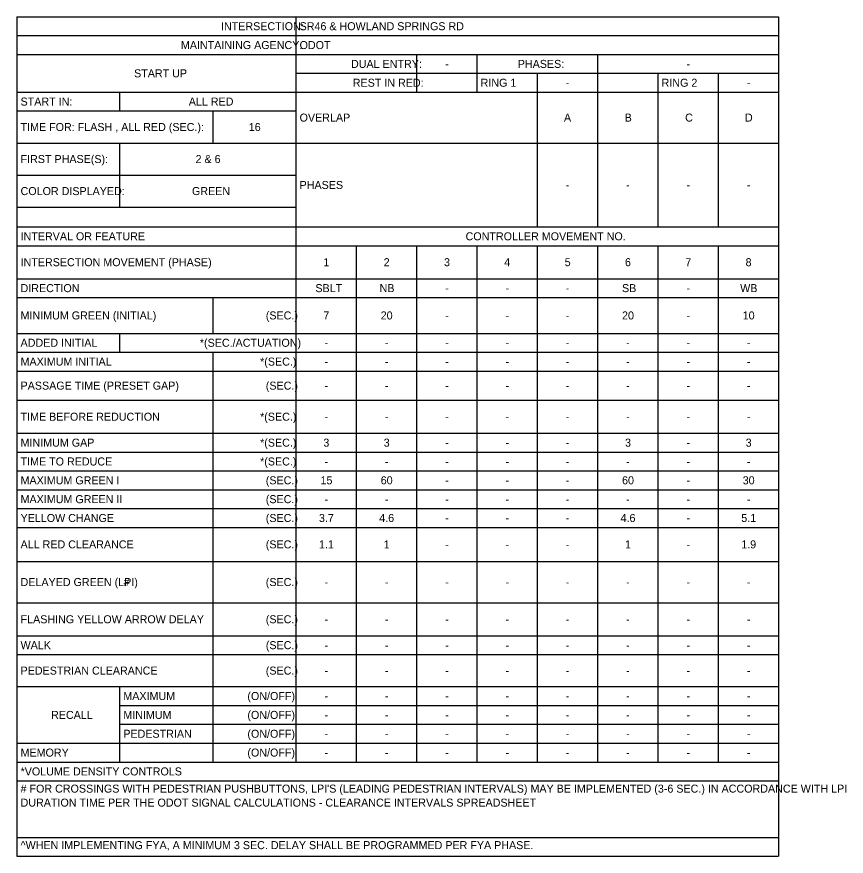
# Model space of a CAD drawing. Extents: x -513 to 1005, y -278 to 699.
# Drawn here: x -513 to -295.6, y -233.4 to -13.3 of the extents above; entities that cross this region are included whole.
import ezdxf

# ---------------------------------------------------------------- set-up
doc = ezdxf.new("R2010")
doc.units = 0
doc.layers.add('SG_P_Poles', color=7, linetype='Continuous')

msp = doc.modelspace()

# ---------------------------------------------------------------- linework, layer by layer
at = {"layer": 'SG_P_Poles'}
for p, q in [((-512.98, -13.26), (-313.35, -13.26)), ((-512.98, -13.26), (-512.98, -233.38)), ((-439.85, -13.26), (-439.85, -208.68)), ((-313.35, -13.26), (-313.35, -233.38)), ((-512.98, -18.2), (-313.35, -18.2)), ((-512.98, -23.14), (-313.35, -23.14)), ((-408.22, -23.14), (-408.22, -33.02)), ((-392.41, -23.14), (-392.41, -33.02)), ((-360.79, -23.14), (-360.79, -68.35)), ((-439.85, -28.08), (-313.35, -28.08)), ((-376.6, -28.08), (-376.6, -68.35)), ((-344.98, -28.08), (-344.98, -68.35)), ((-329.17, -28.08), (-329.17, -68.35)), ((-512.98, -33.02), (-313.35, -33.02)), ((-486.05, -33.02), (-486.05, -37.96)), ((-512.98, -37.96), (-439.85, -37.96)), ((-461.59, -37.96), (-461.59, -46.36)), ((-512.98, -46.36), (-313.35, -46.36)), ((-486.05, -46.36), (-486.05, -63.16)), ((-512.98, -54.76), (-439.85, -54.76)), ((-512.98, -63.16), (-439.85, -63.16)), ((-512.98, -68.35), (-313.35, -68.35)), ((-512.98, -73.29), (-313.35, -73.29)), ((-424.04, -73.29), (-424.04, -208.68)), ((-408.22, -73.29), (-408.22, -208.68)), ((-392.41, -73.29), (-392.41, -208.68)), ((-376.6, -73.29), (-376.6, -208.68)), ((-360.79, -73.29), (-360.79, -208.68)), ((-344.98, -73.29), (-344.98, -208.68)), ((-329.17, -73.29), (-329.17, -208.68)), ((-512.98, -81.94), (-313.35, -81.94)), ((-512.98, -86.88), (-313.35, -86.88)), ((-461.59, -86.88), (-461.59, -96.27)), ((-512.98, -96.27), (-313.35, -96.27)), ((-486.05, -96.27), (-486.05, -101.21)), ((-512.98, -101.21), (-313.35, -101.21)), ((-461.59, -101.21), (-461.59, -208.68)), ((-512.98, -106.15), (-313.35, -106.15)), ((-512.98, -113.81), (-313.35, -113.81)), ((-512.98, -122.46), (-313.35, -122.46)), ((-512.98, -127.4), (-313.35, -127.4)), ((-512.98, -132.34), (-313.35, -132.34)), ((-512.98, -137.28), (-313.35, -137.28)), ((-512.98, -142.22), (-313.35, -142.22)), ((-512.98, -147.16), (-313.35, -147.16)), ((-512.98, -156.06), (-313.35, -156.06)), ((-512.98, -166.93), (-313.35, -166.93)), ((-512.98, -175.57), (-313.35, -175.57)), ((-512.98, -180.51), (-313.35, -180.51)), ((-512.98, -188.91), (-313.35, -188.91)), ((-486.05, -188.91), (-486.05, -208.68)), ((-486.05, -193.86), (-313.35, -193.86)), ((-486.05, -198.8), (-313.35, -198.8)), ((-512.98, -203.74), (-313.35, -203.74)), ((-512.98, -208.68), (-313.35, -208.68)), ((-512.98, -213.62), (-313.35, -213.62)), ((-512.98, -228.44), (-313.35, -228.44)), ((-512.98, -233.38), (-313.35, -233.38))]:
    msp.add_line(p, q, dxfattribs=at)

# ---------------------------------------------------------------- texts
for s, p in [('INTERSECTION:', (-459.46, -16.78)), ('SR46 & HOWLAND SPRINGS RD', (-438.86, -16.78)), ('MAINTAINING AGENCY:', (-469.97, -21.72)), ('ODOT', (-438.86, -21.72)), ('DUAL ENTRY:', (-425.39, -26.66)), ('-', (-400.73, -26.66)), ('PHASES:', (-381.68, -26.66)), ('-', (-337.48, -26.66)), ('START UP', (-482.24, -29.13)), ('REST IN RED:', (-424.92, -31.6)), ('RING 1', (-391.42, -31.6)), ('-', (-369.11, -31.6)), ('RING 2', (-343.99, -31.6)), ('-', (-321.67, -31.6)), ('START IN:', (-511.99, -36.54)), ('ALL RED', (-467.9, -36.54)), ('OVERLAP', (-438.86, -40.74)), ('A', (-369.58, -40.74)), ('B', (-353.67, -40.74)), ('C', (-337.82, -40.74)), ('D', (-322.14, -40.74)), ('TIME FOR: FLASH , ALL RED (SEC.):', (-511.99, -43.21)), ('16', (-452.18, -43.21)), ('FIRST PHASE(S):', (-511.99, -51.61)), ('2 & 6', (-466.13, -51.61)), ('PHASES', (-438.86, -58.41)), ('COLOR DISPLAYED:', (-511.99, -60.01)), ('GREEN', (-467.07, -60.01)), ('-', (-369.11, -58.41)), ('-', (-353.3, -58.41)), ('-', (-337.48, -58.41)), ('-', (-321.67, -58.41)), ('INTERVAL OR FEATURE', (-511.99, -71.87)), ('CONTROLLER MOVEMENT NO.', (-395.36, -71.87)), ('INTERSECTION MOVEMENT (PHASE)', (-511.99, -78.66)), ('1', (-432.63, -78.66)), ('2', (-416.82, -78.66)), ('3', (-401.01, -78.66)), ('4', (-385.23, -78.66)), ('5', (-369.38, -78.66)), ('6', (-353.59, -78.66)), ('7', (-337.76, -78.66)), ('8', (-321.97, -78.66)), ('DIRECTION', (-511.99, -85.46)), ('SBLT', (-434.73, -85.46)), ('NB', (-417.89, -85.46)), ('SB', (-354.37, -85.46)), ('WB', (-323.39, -85.46)), ('-', (-400.73, -85.46)), ('-', (-384.92, -85.46)), ('-', (-369.11, -85.46)), ('-', (-337.48, -85.46)), ('MINIMUM GREEN (INITIAL)', (-511.99, -92.62)), ('(SEC.)', (-447.72, -92.62)), ('7', (-432.64, -92.62)), ('20', (-417.6, -92.62)), ('-', (-400.73, -92.62)), ('-', (-384.92, -92.62)), ('-', (-369.11, -92.62)), ('20', (-354.35, -92.62)), ('-', (-337.48, -92.62)), ('10', (-322.73, -92.62)), ('ADDED INITIAL', (-511.99, -99.79)), ('*(SEC./ACTUATION)', (-465, -99.79)), ('-', (-432.35, -99.79)), ('-', (-416.54, -99.79)), ('-', (-400.73, -99.79)), ('-', (-384.92, -99.79)), ('-', (-369.11, -99.79)), ('-', (-353.3, -99.79)), ('-', (-337.48, -99.79)), ('-', (-321.67, -99.79)), ('MAXIMUM INITIAL', (-511.99, -104.73)), ('*(SEC.)', (-449.21, -104.73)), ('-', (-432.35, -104.73)), ('-', (-416.54, -104.73)), ('-', (-400.73, -104.73)), ('-', (-384.92, -104.73)), ('-', (-369.11, -104.73)), ('-', (-353.3, -104.73)), ('-', (-337.48, -104.73)), ('-', (-321.67, -104.73)), ('PASSAGE TIME (PRESET GAP)', (-511.99, -111.03)), ('(SEC.)', (-447.72, -111.03)), ('-', (-432.35, -111.03)), ('-', (-416.54, -111.03)), ('-', (-400.73, -111.03)), ('-', (-384.92, -111.03)), ('-', (-369.11, -111.03)), ('-', (-353.3, -111.03)), ('-', (-337.48, -111.03)), ('-', (-321.67, -111.03)), ('TIME BEFORE REDUCTION', (-511.99, -119.18)), ('*(SEC.)', (-449.21, -119.18)), ('-', (-432.35, -119.18)), ('-', (-416.54, -119.18)), ('-', (-400.73, -119.18)), ('-', (-384.92, -119.18)), ('-', (-369.11, -119.18)), ('-', (-353.3, -119.18)), ('-', (-337.48, -119.18)), ('-', (-321.67, -119.18)), ('MINIMUM GAP', (-511.99, -125.98)), ('*(SEC.)', (-449.21, -125.98)), ('3', (-432.63, -125.98)), ('3', (-416.82, -125.98)), ('-', (-400.73, -125.98)), ('-', (-384.92, -125.98)), ('-', (-369.11, -125.98)), ('3', (-353.57, -125.98)), ('-', (-337.48, -125.98)), ('3', (-321.95, -125.98)), ('TIME TO REDUCE', (-511.99, -130.92)), ('*(SEC.)', (-449.21, -130.92)), ('-', (-432.35, -130.92)), ('-', (-416.54, -130.92)), ('-', (-400.73, -130.92)), ('-', (-384.92, -130.92)), ('-', (-369.11, -130.92)), ('-', (-353.3, -130.92)), ('-', (-337.48, -130.92)), ('-', (-321.67, -130.92)), ('MAXIMUM GREEN I', (-511.99, -135.86)), ('(SEC.)', (-447.72, -135.86)), ('15', (-433.38, -135.86)), ('60', (-417.6, -135.86)), ('60', (-354.35, -135.86)), ('30', (-322.73, -135.86)), ('-', (-400.73, -135.86)), ('-', (-384.92, -135.86)), ('-', (-369.11, -135.86)), ('-', (-337.48, -135.86)), ('MAXIMUM GREEN II', (-511.99, -140.8)), ('(SEC.)', (-447.72, -140.8)), ('-', (-432.35, -140.8)), ('-', (-416.54, -140.8)), ('-', (-400.73, -140.8)), ('-', (-384.92, -140.8)), ('-', (-369.11, -140.8)), ('-', (-353.3, -140.8)), ('-', (-337.48, -140.8)), ('-', (-321.67, -140.8)), ('YELLOW CHANGE', (-511.99, -145.74)), ('(SEC.)', (-447.72, -145.74)), ('3.7', (-433.79, -145.74)), ('4.6', (-417.99, -145.74)), ('-', (-400.73, -145.74)), ('-', (-384.92, -145.74)), ('-', (-369.11, -145.74)), ('4.6', (-354.74, -145.74)), ('-', (-337.48, -145.74)), ('5.1', (-323.1, -145.74)), ('ALL RED CLEARANCE', (-511.99, -152.66)), ('(SEC.)', (-447.72, -152.66)), ('1.1', (-433.78, -152.66)), ('1', (-416.82, -152.66)), ('-', (-400.73, -152.66)), ('-', (-384.92, -152.66)), ('-', (-369.11, -152.66)), ('1', (-353.57, -152.66)), ('-', (-337.48, -152.66)), ('1.9', (-323.11, -152.66)), ('DELAYED GREEN (LPI) ', (-511.99, -162.54)), ('#', (-485, -162.54)), ('(SEC.)', (-447.72, -162.54)), ('-', (-432.35, -162.54)), ('-', (-416.54, -162.54)), ('-', (-400.73, -162.54)), ('-', (-384.92, -162.54)), ('-', (-369.11, -162.54)), ('-', (-353.3, -162.54)), ('-', (-337.48, -162.54)), ('-', (-321.67, -162.54)), ('FLASHING YELLOW ARROW DELAY', (-511.99, -172.3)), ('(SEC.)', (-447.72, -172.3)), ('-', (-432.35, -172.3)), ('-', (-416.54, -172.3)), ('-', (-400.73, -172.3)), ('-', (-384.92, -172.3)), ('-', (-369.11, -172.3)), ('-', (-353.3, -172.3)), ('-', (-337.48, -172.3)), ('-', (-321.67, -172.3)), ('WALK', (-511.99, -179.09)), ('(SEC.)', (-447.72, -179.09)), ('-', (-432.35, -179.09)), ('-', (-416.54, -179.09)), ('-', (-400.73, -179.09)), ('-', (-384.92, -179.09)), ('-', (-369.11, -179.09)), ('-', (-353.3, -179.09)), ('-', (-337.48, -179.09)), ('-', (-321.67, -179.09)), ('PEDESTRIAN CLEARANCE', (-511.99, -185.76)), ('(SEC.)', (-447.72, -185.76)), ('-', (-432.35, -185.76)), ('-', (-416.54, -185.76)), ('-', (-400.73, -185.76)), ('-', (-384.92, -185.76)), ('-', (-369.11, -185.76)), ('-', (-353.3, -185.76)), ('-', (-337.48, -185.76)), ('-', (-321.67, -185.76)), ('MAXIMUM', (-485.06, -192.43)), ('(ON/OFF)', (-452.54, -192.43)), ('-', (-432.35, -192.43)), ('-', (-416.54, -192.43)), ('-', (-400.73, -192.43)), ('-', (-384.92, -192.43)), ('-', (-369.11, -192.43)), ('-', (-353.3, -192.43)), ('-', (-337.48, -192.43)), ('-', (-321.67, -192.43)), ('RECALL', (-504, -197.38)), ('MINIMUM', (-485.06, -197.38)), ('(ON/OFF)', (-452.54, -197.38)), ('-', (-432.35, -197.38)), ('-', (-416.54, -197.38)), ('-', (-400.73, -197.38)), ('-', (-384.92, -197.38)), ('-', (-369.11, -197.38)), ('-', (-353.3, -197.38)), ('-', (-337.48, -197.38)), ('-', (-321.67, -197.38)), ('PEDESTRIAN', (-485.06, -202.32)), ('(ON/OFF)', (-452.54, -202.32)), ('-', (-432.35, -202.32)), ('-', (-416.54, -202.32)), ('-', (-400.73, -202.32)), ('-', (-384.92, -202.32)), ('-', (-369.11, -202.32)), ('-', (-353.3, -202.32)), ('-', (-337.48, -202.32)), ('-', (-321.67, -202.32)), ('MEMORY', (-511.99, -207.26)), ('(ON/OFF)', (-452.54, -207.26)), ('-', (-432.35, -207.26)), ('-', (-416.54, -207.26)), ('-', (-400.73, -207.26)), ('-', (-384.92, -207.26)), ('-', (-369.11, -207.26)), ('-', (-353.3, -207.26)), ('-', (-337.48, -207.26)), ('-', (-321.67, -207.26)), ('*VOLUME DENSITY CONTROLS', (-511.99, -212.2)), ("# FOR CROSSINGS WITH PEDESTRIAN PUSHBUTTONS, LPI'S (LEADING PEDESTRIAN INTERVALS) MAY BE IMPLEMENTED (3-6 SEC.) IN ACCORDANCE WITH LPI ", (-511.99, -216.71)), ('DURATION TIME PER THE ODOT SIGNAL CALCULATIONS - CLEARANCE INTERVALS SPREADSHEET', (-511.99, -220.38)), ('^ WHEN IMPLEMENTING FYA, A MINIMUM 3 SEC. DELAY SHALL BE PROGRAMMED PER FYA PHASE.', (-511.99, -231.53))]:
    msp.add_text(s, height=2.1, dxfattribs=at).set_placement(p)

doc.saveas('drawing.dxf')
